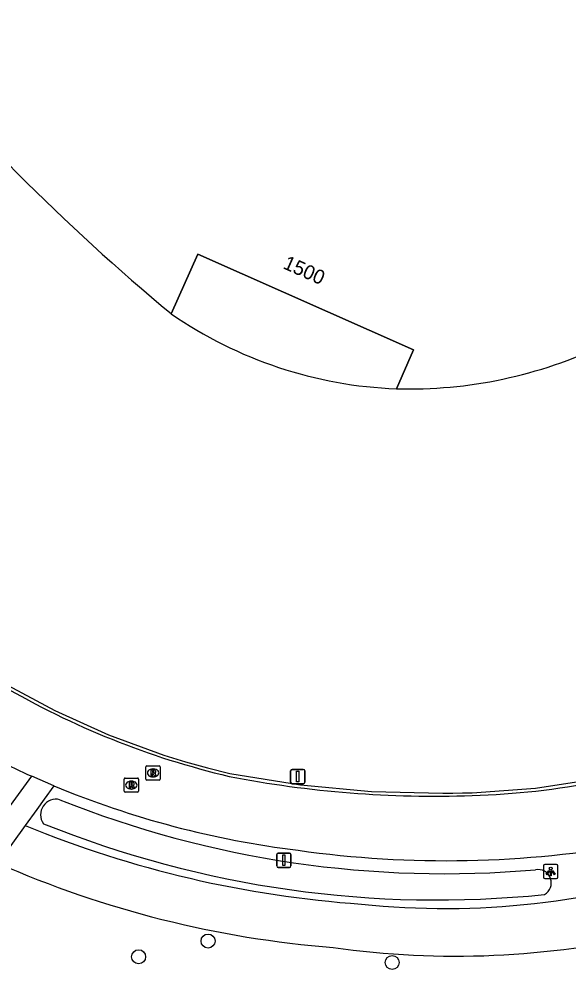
# Model space of a CAD drawing. Extents: x 155018 to 156648, y 383980 to 385733.
# Drawn here: x 155810.4 to 155848.9, y 384250.7 to 384316.9 of the extents above; entities that cross this region are included whole.
import ezdxf

# ---------------------------------------------------------------- set-up
doc = ezdxf.new("R2010")
doc.units = 0
for name, color, linetype in [('IMGEO_Boom', 7, 'Continuous'), ('IMGEO_Groenvoorziening', 7, 'Continuous'), ('IMGEO_Lichtpunt', 7, 'Continuous'), ('IMGEO_Lijnafwatering', 7, 'Continuous'), ('IMGEO_Pand', 7, 'Continuous'), ('IMGEO_Pand_nummerreeks', 7, 'Continuous'), ('IMGEO_Pand_overbouw', 7, 'Continuous'), ('IMGEO_Rijbaan_lokaal_gesloten', 7, 'Continuous'), ('IMGEO_Rioolput', 7, 'Continuous'), ('IMGEO_Verkeersbordpaal', 7, 'Continuous'), ('IMGEO_Voetpad_halfverhard', 7, 'Continuous'), ('IMGEO_Waterloop', 7, 'Continuous')]:
    doc.layers.add(name, color=color, linetype=linetype)

msp = doc.modelspace()

# ---------------------------------------------------------------- linework, layer by layer
at = {"layer": 'IMGEO_Boom'}
for centre in [(155823.651, 384252.272), (155818.785, 384251.17), (155836.557, 384250.771)]:
    msp.add_circle(centre, 0.489, dxfattribs=at)
at = {"layer": 'IMGEO_Groenvoorziening'}
for centre, radius, start, end in [((155839.603, 384330.316), 75.63, 247.63496, 266.05689), ((155838.133, 384324.163), 72.569, 246.24875, 265.49317), ((155840.286, 384310.367), 55.813, 263.94829, 288.92814), ((155841.011, 384312.342), 61.128, 261.93116, 283.06837)]:
    msp.add_arc(centre, radius, start, end, dxfattribs=at)
at = {"layer": 'IMGEO_Lichtpunt'}
for p, q in [((155847.171, 384257.551), (155847.171, 384256.744)), ((155847.171, 384257.551), (155847.171, 384256.744)), ((155848.073, 384257.646), (155847.265, 384257.646)), ((155848.073, 384257.646), (155847.265, 384257.646)), ((155848.167, 384256.744), (155848.167, 384257.551)), ((155848.167, 384256.744), (155848.167, 384257.551)), ((155847.265, 384256.65), (155848.073, 384256.65)), ((155847.265, 384256.65), (155848.073, 384256.65))]:
    msp.add_line(p, q, dxfattribs=at)
for points in [[(155847.545, 384257.215), (155847.584, 384257.187), (155847.396, 384256.925), (155847.358, 384256.952), (155847.545, 384257.215)], [(155847.647, 384257.167), (155847.694, 384257.167), (155847.694, 384256.845), (155847.647, 384256.845), (155847.647, 384257.167)], [(155847.757, 384257.187), (155847.795, 384257.214), (155847.982, 384256.952), (155847.943, 384256.924), (155847.757, 384257.187)]]:
    msp.add_lwpolyline(points, dxfattribs=at)
msp.add_circle((155847.67, 384257.349), 0.0994, dxfattribs=at)
for centre, start, end in [((155847.265, 384257.551), 90, 180), ((155847.265, 384257.551), 90, 180), ((155848.073, 384257.551), 0, 90), ((155848.073, 384257.551), 0, 90), ((155847.265, 384256.744), 180, 270), ((155847.265, 384256.744), 180, 270), ((155848.073, 384256.744), 270, 0), ((155848.073, 384256.744), 270, 360)]:
    msp.add_arc(centre, 0.0946, start, end, dxfattribs=at)
at = {"layer": 'IMGEO_Lijnafwatering'}
for points in [[(155802.987, 384274.421), (155805.051, 384273.025), (155807.149, 384271.68), (155809.278, 384270.386), (155812.907, 384268.427), (155816.668, 384266.734), (155820.54, 384265.316)], [(155840.121, 384262.63), (155840.799, 384262.639), (155841.477, 384262.654), (155842.155, 384262.675), (155846.597, 384262.989), (155850.999, 384263.661), (155855.332, 384264.686), (155859.568, 384266.058)], [(155820.54, 384265.316), (155822.074, 384264.839), (155823.621, 384264.406), (155825.179, 384264.016), (155830.125, 384263.219), (155835.113, 384262.757), (155840.121, 384262.63)]]:
    msp.add_lwpolyline(points, dxfattribs=at)
at = {"layer": 'IMGEO_Pand'}
msp.add_lwpolyline([(155821.077, 384296.245), (155822.941, 384300.446), (155838.061, 384293.72), (155836.857, 384290.997)], dxfattribs=at)
for centre, radius, start, end in [((155924.104, 384419.823), 160.891, 219.75412, 230.18215), ((155837.737, 384322.641), 31.656, 268.4077, 295.5941)]:
    msp.add_arc(centre, radius, start, end, dxfattribs=at)
at = {"layer": 'IMGEO_Pand_overbouw'}
msp.add_lwpolyline([(155836.857, 384290.997), (155838.061, 384293.72), (155822.941, 384300.446), (155821.077, 384296.245)], dxfattribs=at)
msp.add_arc((155837.99, 384320.752), 29.777, 235.38953, 267.81902, dxfattribs=at)
at = {"layer": 'IMGEO_Rijbaan_lokaal_gesloten'}
msp.add_lwpolyline([(155812.85, 384263.155), (155811.293, 384263.827)], dxfattribs=at)
for centre, radius, start, end in [((155838.308, 384319.82), 57.527, 239.57658, 256.76863), ((155838.24, 384324.112), 66.033, 241.45225, 245.91587), ((155840.492, 384317.734), 55.284, 271.73066, 290.30741), ((155839.502, 384337.19), 74.762, 258.92501, 272.03874), ((155837.979, 384323.606), 65.466, 247.42756, 262.96403), ((155840.345, 384332.577), 74.67, 262.00578, 280.26273)]:
    msp.add_arc(centre, radius, start, end, dxfattribs=at)
at = {"layer": 'IMGEO_Rioolput'}
for p, q in [((155819.295, 384263.634), (155819.295, 384264.486)), ((155819.37, 384264.56), (155820.222, 384264.56)), ((155820.296, 384264.486), (155820.296, 384263.634)), ((155819.806, 384263.78), (155819.781, 384263.78)), ((155819.783, 384264.34), (155819.808, 384264.34)), ((155817.773, 384262.778), (155817.773, 384263.63)), ((155817.848, 384263.704), (155818.7, 384263.704)), ((155818.261, 384263.484), (155818.286, 384263.484)), ((155818.774, 384263.63), (155818.774, 384262.778)), ((155820.222, 384263.56), (155819.37, 384263.56)), ((155818.7, 384262.704), (155817.848, 384262.704)), ((155818.284, 384262.924), (155818.259, 384262.924))]:
    msp.add_line(p, q, dxfattribs=at)
for points in [[(155819.295, 384263.634), (155819.295, 384264.486)], [(155819.37, 384264.56), (155820.222, 384264.56)], [(155820.296, 384264.486), (155820.296, 384263.634)], [(155819.884, 384264.258), (155819.632, 384264.26), (155819.632, 384263.86)], [(155819.632, 384263.86), (155819.756, 384263.86), (155819.756, 384264.022), (155819.767, 384264.022)], [(155819.81, 384264.179), (155819.756, 384264.179), (155819.756, 384264.098)], [(155819.756, 384264.098), (155819.808, 384264.098)], [(155819.814, 384263.993), (155819.885, 384263.86), (155820.025, 384263.86), (155819.96, 384263.986)], [(155817.773, 384262.778), (155817.773, 384263.63)], [(155817.848, 384263.704), (155818.7, 384263.704)], [(155818.362, 384263.402), (155818.11, 384263.404), (155818.11, 384263.004)], [(155818.11, 384263.004), (155818.234, 384263.004), (155818.234, 384263.166), (155818.245, 384263.166)], [(155818.288, 384263.323), (155818.234, 384263.323), (155818.234, 384263.242)], [(155818.234, 384263.242), (155818.286, 384263.242)], [(155818.292, 384263.137), (155818.363, 384263.004), (155818.503, 384263.004), (155818.438, 384263.13)], [(155818.774, 384263.63), (155818.774, 384262.778)], [(155820.222, 384263.56), (155819.37, 384263.56)], [(155818.7, 384262.704), (155817.848, 384262.704)]]:
    msp.add_lwpolyline(points, dxfattribs=at)
for centre, radius, start, end in [((155819.372, 384264.484), 0.0765, 91.55205, 178.44795), ((155819.372, 384264.484), 0.0765, 91.55205, 178.44795), ((155820.22, 384264.484), 0.0765, 1.55205, 88.44795), ((155820.22, 384264.484), 0.0765, 1.55205, 88.44795), ((155819.766, 384263.969), 0.0533, 26.02933, 88.69889), ((155819.792, 384264.287), 0.19, 274.7715, 282.96867), ((155819.816, 384264.083), 0.0964, 77.00612, 93.18647), ((155819.83, 384264.14), 0.0378, 276.66336, 79.67722), ((155819.883, 384264.148), 0.109, 350.36119, 89.41601), ((155819.881, 384264.148), 0.112, 277.58423, 350.98172), ((155819.865, 384263.933), 0.108, 29.51342, 73.79051), ((155817.85, 384263.628), 0.0765, 91.55205, 178.44795), ((155817.85, 384263.628), 0.0765, 91.55205, 178.44795), ((155818.244, 384263.113), 0.0533, 26.02933, 88.69889), ((155818.27, 384263.431), 0.19, 274.7715, 282.96867), ((155818.294, 384263.227), 0.0964, 77.00612, 93.18647), ((155818.308, 384263.284), 0.0378, 276.66336, 79.67722), ((155818.361, 384263.292), 0.109, 350.36119, 89.41601), ((155818.359, 384263.292), 0.112, 277.58423, 350.98172), ((155818.343, 384263.077), 0.108, 29.51342, 73.79051), ((155818.698, 384263.628), 0.0765, 1.55205, 88.44795), ((155818.698, 384263.628), 0.0765, 1.55205, 88.44795), ((155819.372, 384263.636), 0.0765, 181.55205, 268.44795), ((155819.372, 384263.636), 0.0765, 181.55205, 268.44795), ((155820.22, 384263.636), 0.0765, 271.55205, 358.44795), ((155820.22, 384263.636), 0.0765, 271.55205, 358.44795), ((155817.85, 384262.78), 0.0765, 181.55205, 268.44795), ((155817.85, 384262.78), 0.0765, 181.55205, 268.44795), ((155818.698, 384262.78), 0.0765, 271.55205, 358.44795), ((155818.698, 384262.78), 0.0765, 271.55205, 358.44795)]:
    msp.add_arc(centre, radius, start, end, dxfattribs=at)
for centre, major_axis, ratio, start_param, end_param in [((155819.782, 384264.06), (-0.387, 0.002), 0.722429, 4.712389, 7.853982), ((155819.807, 384264.06), (-0.39, 0.002), 0.717154, 1.570796, 4.712389), ((155818.26, 384263.204), (-0.387, 0.002), 0.722429, 4.712389, 7.853982), ((155818.285, 384263.204), (-0.39, 0.002), 0.717154, 1.570796, 4.712389)]:
    msp.add_ellipse(centre, major_axis=major_axis, ratio=ratio, start_param=start_param, end_param=end_param, dxfattribs=at)
at = {"layer": 'IMGEO_Verkeersbordpaal'}
for p, q in [((155829.44, 384263.404), (155829.44, 384264.204)), ((155829.44, 384264.204), (155829.44, 384263.404)), ((155829.54, 384264.304), (155830.33, 384264.304)), ((155830.33, 384264.304), (155829.54, 384264.304)), ((155830.43, 384264.204), (155830.43, 384263.404)), ((155830.43, 384263.404), (155830.43, 384264.204)), ((155830.33, 384263.304), (155829.54, 384263.304)), ((155829.54, 384263.304), (155830.33, 384263.304)), ((155828.475, 384257.534), (155828.475, 384258.334)), ((155828.475, 384258.334), (155828.475, 384257.534)), ((155828.575, 384258.434), (155829.365, 384258.434)), ((155829.365, 384258.434), (155828.575, 384258.434)), ((155829.465, 384258.334), (155829.465, 384257.534)), ((155829.465, 384257.534), (155829.465, 384258.334)), ((155829.365, 384257.434), (155828.575, 384257.434)), ((155828.575, 384257.434), (155829.365, 384257.434))]:
    msp.add_line(p, q, dxfattribs=at)
for points in [[(155829.86, 384264.179), (155830.01, 384264.179), (155830.01, 384263.429), (155829.86, 384263.429), (155829.86, 384264.179)], [(155828.895, 384258.309), (155829.045, 384258.309), (155829.045, 384257.559), (155828.895, 384257.559), (155828.895, 384258.309)]]:
    msp.add_lwpolyline(points, dxfattribs=at)
for centre, start, end in [((155829.54, 384264.204), 90, 180), ((155829.54, 384264.204), 90, 180), ((155830.33, 384264.204), 0, 90), ((155830.33, 384264.204), 360, 90), ((155829.54, 384263.404), 180, 270), ((155829.54, 384263.404), 180, 270), ((155830.33, 384263.404), 270, 0), ((155830.33, 384263.404), 270, 0), ((155828.575, 384258.334), 90, 180), ((155828.575, 384258.334), 90, 180), ((155829.365, 384258.334), 0, 90), ((155829.365, 384258.334), 360, 90), ((155828.575, 384257.534), 180, 270), ((155828.575, 384257.534), 180, 270), ((155829.365, 384257.534), 270, 0), ((155829.365, 384257.534), 270, 0)]:
    msp.add_arc(centre, 0.1, start, end, dxfattribs=at)
at = {"layer": 'IMGEO_Voetpad_halfverhard'}
for points in [[(155809.235, 384261.008), (155811.293, 384263.827)], [(155812.85, 384263.155), (155812.169, 384262.22), (155811.649, 384261.507), (155810.825, 384260.375)], [(155810.825, 384260.375), (155808.905, 384257.741)]]:
    msp.add_lwpolyline(points, dxfattribs=at)
at = {"layer": 'IMGEO_Waterloop'}
for centre, radius, start, end in [((155812.991, 384261.134), 1.081, 75.88665, 215.93561), ((155840.201, 384329.531), 72.539, 248.19351, 275.068), ((155839.711, 384328.998), 73.848, 248.05786, 275.84098), ((155846.777, 384256.355), 0.936, 298.64359, 100.36374)]:
    msp.add_arc(centre, radius, start, end, dxfattribs=at)

# ---------------------------------------------------------------- texts
at = {"layer": 'IMGEO_Pand_nummerreeks'}
msp.add_text('1500', height=1, rotation=336.01599, dxfattribs=at).set_placement((155828.837, 384299.465))

doc.saveas('drawing.dxf')
